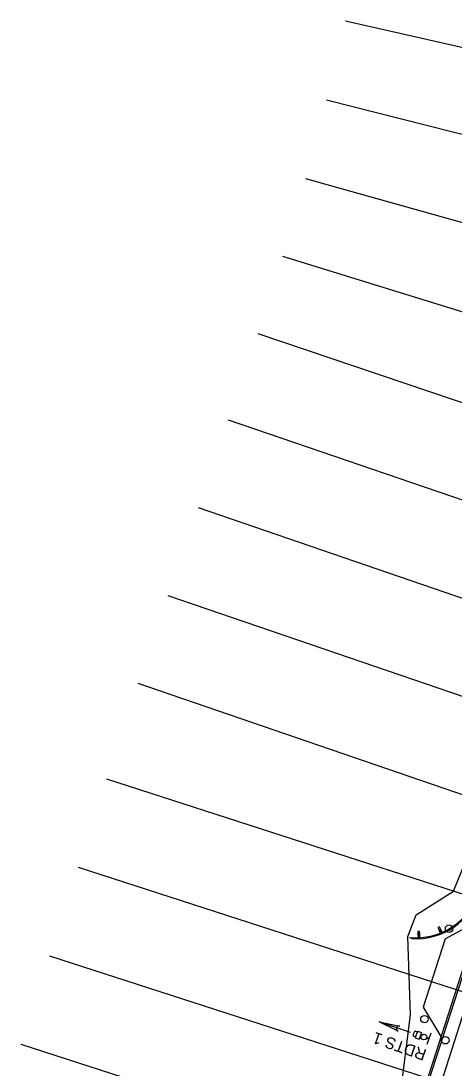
# Model space of a CAD drawing. Extents: x 157201 to 163282, y 424960 to 427200.
# Drawn here: x 157224.1 to 157340.7, y 426228.2 to 426510.1 of the extents above; entities that cross this region are included whole.
import ezdxf

# ---------------------------------------------------------------- set-up
doc = ezdxf.new("R2010")
doc.units = 0
for name, color, linetype in [('Default', 7, 'Continuous'), ('PM_X_Stop_Line', 7, 'Continuous'), ('RW_X_CL_100_Distances', 7, 'Continuous'), ('RW_X_CL_100_Stations', 7, 'Continuous'), ('SC_Scratch1', 7, 'Continuous'), ('SN_X_Public', 7, 'Continuous'), ('UT_X_Electric', 7, 'Continuous')]:
    doc.layers.add(name, color=color, linetype=linetype)

msp = doc.modelspace()

# ---------------------------------------------------------------- linework, layer by layer
at = {"layer": 'Default'}
for p, q in [((157311.42, 426510.09), (157545.56, 426457.4)), ((157306.34, 426488.83), (157539.03, 426430.03)), ((157300.71, 426467.71), (157531.78, 426402.84)), ((157294.53, 426446.74), (157523.82, 426375.84)), ((157287.8, 426425.95), (157515.15, 426349.07)), ((157279.85, 426402.74), (157506.91, 426324.97)), ((157271.75, 426379.09), (157498.81, 426301.32)), ((157263.65, 426355.43), (157490.71, 426277.67)), ((157255.55, 426331.78), (157482.61, 426254.02)), ((157247.12, 426306.04), (157475.49, 426232.25)), ((157239.43, 426282.25), (157467.81, 426208.46)), ((157231.75, 426258.46), (157460.12, 426184.67)), ((157224.06, 426234.67), (157452.43, 426160.88))]:
    msp.add_line(p, q, dxfattribs=at)
at = {"layer": 'PM_X_Stop_Line'}
for p, q in [((157338.29, 426262.96), (157347.23, 426267.86)), ((157338.29, 426262.96), (157332.37, 426244.62)), ((157332.37, 426244.62), (157337.16, 426236.68))]:
    msp.add_line(p, q, dxfattribs=at)
at = {"layer": 'RW_X_CL_100_Distances'}
for centre in [(157339.33, 426265.74), (157332.69, 426241.39), (157338.32, 426235.7)]:
    msp.add_circle(centre, 1, dxfattribs=at)
at = {"layer": 'RW_X_CL_100_Stations'}
msp.add_lwpolyline([(157375.4, 426349.93), (157355.49, 426291.81), (157332.81, 426221.6)], dxfattribs=at)
at = {"layer": 'SC_Scratch1'}
for p, q in [((157328.97, 426237.75), (157320.53, 426240.69)), ((157325.61, 426238.18), (157320.53, 426240.69)), ((157320.53, 426240.69), (157326.07, 426239.5)), ((157330.83, 426238.19), (157330.2, 426236.36)), ((157330.29, 426238.12), (157330.75, 426237.96)), ((157330.83, 426238.19), (157331.92, 426237.82)), ((157331.92, 426237.82), (157331.28, 426235.99)), ((157334.42, 426237.64), (157333.36, 426234.58)), ((157329.82, 426236.76), (157330.27, 426236.6)), ((157330.2, 426236.36), (157331.28, 426235.99)), ((157331.81, 426236.7), (157331.56, 426236.79)), ((157331.89, 426236.93), (157331.64, 426237.02)), ((157333.85, 426236), (157333.22, 426236.21)), ((157333.93, 426236.22), (157333.3, 426236.44))]:
    msp.add_line(p, q, dxfattribs=at)
for points in [[(157330.46, 426269.42), (157340.56, 426275.84), (157350.12, 426299.39), (157352.46, 426325.02)], [(157326.55, 426223.35), (157328.94, 426242.56), (157328.23, 426263.59), (157330.46, 426269.42)]]:
    msp.add_lwpolyline(points, dxfattribs=at)
msp.add_circle((157332.56, 426236.57), 0.757, dxfattribs=at)
msp.add_arc((157325.84, 426238.84), 0.703, 70.7812, 250.7812, dxfattribs=at)
msp.add_ellipse((157330.05, 426237.44), major_axis=(0.236, 0.681), ratio=0.45371, start_param=0, end_param=3.141593, dxfattribs=at)
at = {"layer": 'SN_X_Public'}
msp.add_line((157381.52, 426363.16), (157322, 426176.75), dxfattribs=at)
msp.add_lwpolyline([(157379.62, 426363.81), (157355.02, 426291.96), (157332.33, 426221.75)], dxfattribs=at)
at = {"layer": 'UT_X_Electric'}
for p, q in [((157337.44, 426264.73), (157336.59, 426265.47)), ((157336.97, 426264.54), (157337.06, 426265.66)), ((157328.71, 426263.39), (157329.37, 426263.06)), ((157331.48, 426263.33), (157330.93, 426264.31)), ((157330.98, 426263.31), (157331.43, 426264.33))]:
    msp.add_line(p, q, dxfattribs=at)
for points in [[(157336.8, 426266.27), (157336.34, 426266.08), (157336.59, 426265.47), (157337.06, 426265.66)], [(157337.06, 426265.66), (157336.59, 426265.47), (157336.97, 426264.54), (157337.44, 426264.73)], [(157331.41, 426265), (157330.91, 426264.98), (157330.93, 426264.31), (157331.43, 426264.33)], [(157331.43, 426264.33), (157330.93, 426264.31), (157330.98, 426263.31), (157331.48, 426263.33)]]:
    msp.add_lwpolyline(points, close=True, dxfattribs=at)
for radius, start in [(17.72, 264.3075), (18, 266.521)]:
    msp.add_arc((157330.47, 426281.02), radius, start, 342.0943, dxfattribs=at)

# ---------------------------------------------------------------- texts
at = {"layer": 'SC_Scratch1'}
msp.add_text('RDTS 1', height=3.125, rotation=160.7812, dxfattribs=at).set_placement((157333.51, 426233.09))

doc.saveas('drawing.dxf')
